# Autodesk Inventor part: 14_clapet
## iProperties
Created: 2002-11
Part Number: 14_clapet
Material: Par défaut
Document SubType Name: Modélisation
Designer: FIEVET
Control State: 0
Master: False
Checked Out: False
Shininess: 20.0
Length Units: 11269
Angle Units: 11279
Time Units: 11290
Mass Units: 11283
Length Display Precision: 3
Angle Display Precision: 2
Compacted: True
Density: 0.0
Volumn: 0.0
Area: 0.0
PropertySet Name: Model Information
Author: FIEVET
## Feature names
1. Révolution1 [Revolution]
